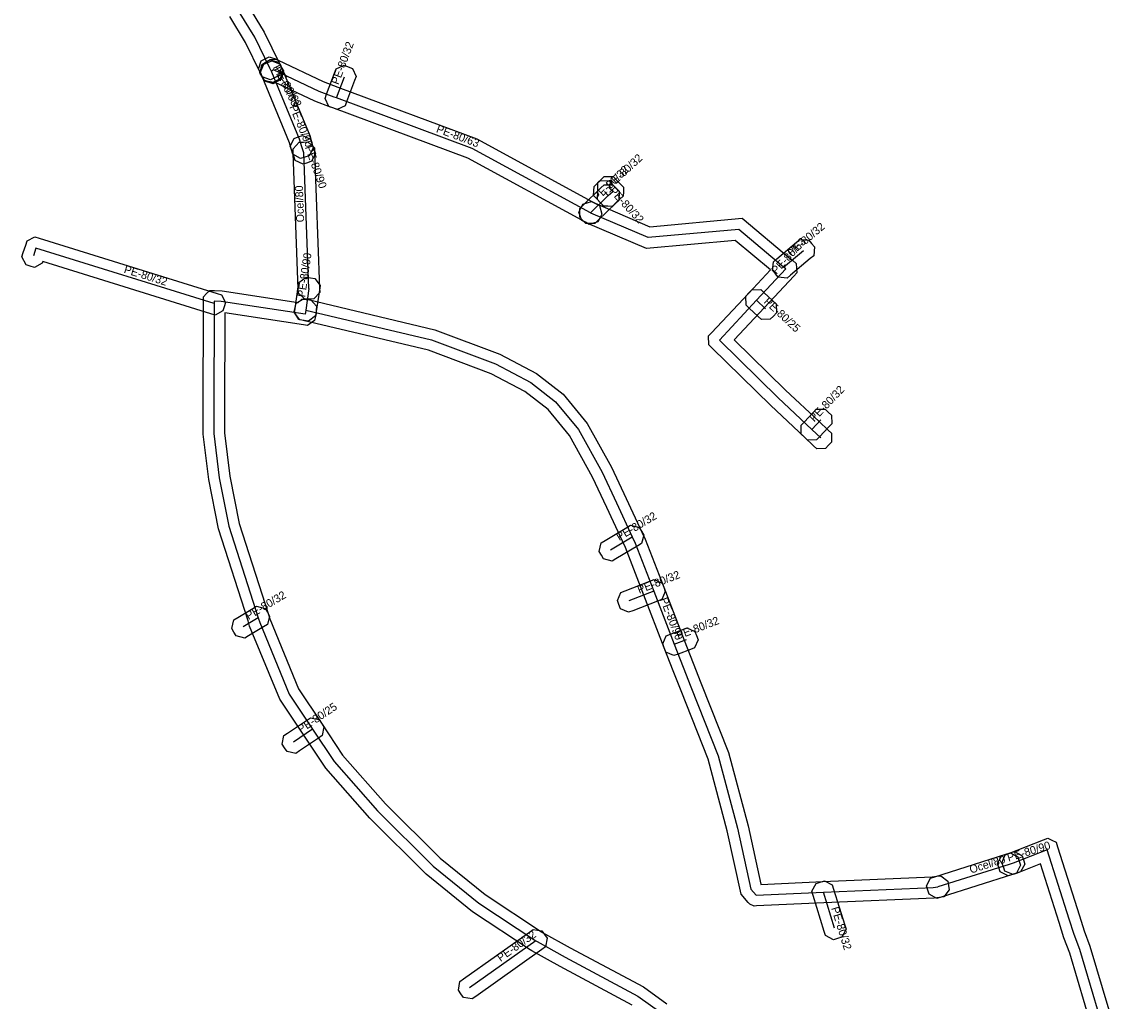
# Model space of a CAD drawing. Extents: x -569373 to -565022, y -1135090 to -1131496.
# Drawn here: x -568946 to -568842.9, y -1132989.8 to -1132898.1 of the extents above; entities that cross this region are included whole.
import ezdxf

# ---------------------------------------------------------------- set-up
doc = ezdxf.new("R2010")
doc.units = 0
for name, color, linetype in [('1', 7, 'Continuous'), ('24', 7, 'Continuous'), ('30', 7, 'Continuous')]:
    doc.layers.add(name, color=color, linetype=linetype)

msp = doc.modelspace()

# ---------------------------------------------------------------- linework, layer by layer
at = {"layer": '1'}
for points in [[(-568924.816, -1132896.447), (-568923.252, -1132899.009), (-568921.811, -1132901.961), (-568921.63, -1132902.333), (-568921.899, -1132903.117), (-568922.271, -1132903.299), (-568922.643, -1132903.48), (-568923.427, -1132903.211), (-568923.609, -1132902.839), (-568925.008, -1132899.971), (-568926.484, -1132897.553)], [(-568888.759, -1132990.191), (-568895.52, -1132986.587), (-568898.167, -1132985.102), (-568898.327, -1132985.004), (-568903.711, -1132981.458), (-568908.079, -1132977.925), (-568913.349, -1132972.685), (-568917.485, -1132967.98), (-568919.542, -1132964.895), (-568921.797, -1132961.512), (-568924.61, -1132954.672), (-568924.763, -1132954.194), (-568927.53, -1132945.551), (-568928.448, -1132940.929), (-568928.97, -1132936.679), (-568928.96, -1132934.517), (-568928.95, -1132924.45), (-568928.95, -1132924.23), (-568928.95, -1132923.807), (-568928.647, -1132923.513), (-568928.343, -1132923.218), (-568927.921, -1132923.23), (-568927.18, -1132923.252), (-568920.055, -1132924.331), (-568919.729, -1132924.032), (-568919.315, -1132924.051), (-568918.901, -1132924.07), (-568918.342, -1132924.681), (-568918.361, -1132925.095), (-568918.375, -1132925.408), (-568918.437, -1132925.669), (-568918.526, -1132926.049), (-568919.174, -1132926.487), (-568919.56, -1132926.429), (-568926.951, -1132925.31), (-568926.96, -1132934.523), (-568926.97, -1132936.561), (-568926.472, -1132940.611), (-568925.59, -1132945.049), (-568922.857, -1132953.586), (-568922.73, -1132953.988), (-568920.023, -1132960.568), (-568917.878, -1132963.785), (-568915.895, -1132966.76), (-568911.891, -1132971.315), (-568906.741, -1132976.435), (-568902.529, -1132979.842), (-568897.253, -1132983.316), (-568897.153, -1132983.378), (-568894.56, -1132984.833), (-568887.701, -1132988.489), (-568885.491, -1132990.075)], [(-568844.847, -1132995.079), (-568847.737, -1132985.313), (-568848.284, -1132983.902), (-568848.746, -1132982.443), (-568850.482, -1132976.967), (-568852.669, -1132977.813), (-568853.055, -1132977.962), (-568853.813, -1132977.627), (-568853.963, -1132977.241), (-568854.112, -1132976.855), (-568853.777, -1132976.097), (-568853.391, -1132975.947), (-568850.211, -1132974.717), (-568849.807, -1132974.561), (-568849.417, -1132974.748), (-568849.027, -1132974.936), (-568848.897, -1132975.348), (-568846.84, -1132981.839), (-568846.396, -1132983.238), (-568845.843, -1132984.667), (-568842.933, -1132994.501)]]:
    msp.add_lwpolyline(points, dxfattribs=at)
for points in [[(-568923.279, -1132903.498), (-568923.464, -1132903.127), (-568923.484, -1132903.087), (-568923.604, -1132902.847), (-568923.79, -1132902.477), (-568923.528, -1132901.691), (-568923.157, -1132901.506), (-568922.787, -1132901.32), (-568922.001, -1132901.582), (-568921.816, -1132901.953), (-568921.696, -1132902.193), (-568921.676, -1132902.233), (-568921.49, -1132902.603), (-568921.752, -1132903.389), (-568922.123, -1132903.574), (-568922.493, -1132903.76)], [(-568923.193, -1132903.618), (-568923.394, -1132903.256), (-568923.444, -1132903.166), (-568923.645, -1132902.804), (-568923.418, -1132902.007), (-568923.056, -1132901.806), (-568922.694, -1132901.605), (-568921.897, -1132901.832), (-568921.696, -1132902.194), (-568921.646, -1132902.284), (-568921.445, -1132902.646), (-568921.672, -1132903.443), (-568922.034, -1132903.644), (-568922.396, -1132903.845)], [(-568918.488, -1132905.493), (-568922.293, -1132903.693), (-568922.372, -1132903.744), (-568923.182, -1132903.572), (-568923.408, -1132903.225), (-568923.634, -1132902.878), (-568923.462, -1132902.068), (-568923.115, -1132901.842), (-568922.915, -1132901.712), (-568922.697, -1132901.57), (-568922.177, -1132901.535), (-568921.942, -1132901.646), (-568917.712, -1132903.647), (-568916.335, -1132904.155), (-568916.103, -1132904.246), (-568903.324, -1132909.008), (-568892.182, -1132915.072), (-568891.818, -1132915.27), (-568891.584, -1132916.064), (-568891.782, -1132916.428), (-568891.98, -1132916.792), (-568892.774, -1132917.026), (-568893.138, -1132916.828), (-568904.156, -1132910.832), (-568916.817, -1132906.114), (-568917.045, -1132906.025)], [(-568920.567, -1132910.444), (-568920.681, -1132910.046), (-568920.876, -1132909.37), (-568923.444, -1132903.152), (-568923.602, -1132902.769), (-568923.285, -1132902.004), (-568922.902, -1132901.846), (-568922.519, -1132901.688), (-568921.754, -1132902.005), (-568921.596, -1132902.388), (-568918.984, -1132908.71), (-568918.759, -1132909.494), (-568918.645, -1132909.892), (-568919.046, -1132910.617), (-568919.444, -1132910.731), (-568919.842, -1132910.845)], [(-568917.542, -1132905.218), (-568917.397, -1132904.83), (-568916.657, -1132902.85), (-568916.512, -1132902.462), (-568915.758, -1132902.118), (-568915.37, -1132902.263), (-568914.982, -1132902.408), (-568914.638, -1132903.162), (-568914.783, -1132903.55), (-568915.523, -1132905.53), (-568915.668, -1132905.918), (-568916.422, -1132906.262), (-568916.81, -1132906.117), (-568917.198, -1132905.972)], [(-568920.335, -1132911.033), (-568920.473, -1132910.642), (-568920.663, -1132910.102), (-568920.801, -1132909.711), (-568920.443, -1132908.965), (-568920.052, -1132908.827), (-568919.661, -1132908.689), (-568918.915, -1132909.047), (-568918.777, -1132909.438), (-568918.587, -1132909.978), (-568918.449, -1132910.369), (-568918.807, -1132911.115), (-568919.198, -1132911.253), (-568919.589, -1132911.391)], [(-568920.044, -1132923.481), (-568920.059, -1132923.067), (-568920.529, -1132910.347), (-568920.544, -1132909.933), (-568919.981, -1132909.326), (-568919.567, -1132909.311), (-568919.153, -1132909.296), (-568918.546, -1132909.859), (-568918.531, -1132910.273), (-568918.061, -1132922.993), (-568918.046, -1132923.407), (-568918.609, -1132924.014), (-568919.023, -1132924.029), (-568919.437, -1132924.044)], [(-568893.655, -1132915.524), (-568893.358, -1132915.234), (-568891.688, -1132913.604), (-568891.392, -1132913.315), (-568890.564, -1132913.325), (-568890.274, -1132913.622), (-568889.985, -1132913.918), (-568889.995, -1132914.746), (-568890.292, -1132915.036), (-568891.962, -1132916.666), (-568892.258, -1132916.955), (-568893.086, -1132916.945), (-568893.376, -1132916.648), (-568893.665, -1132916.352)], [(-568891.444, -1132915.302), (-568891.725, -1132914.998), (-568892.085, -1132914.608), (-568892.366, -1132914.304), (-568892.332, -1132913.476), (-568892.028, -1132913.195), (-568891.724, -1132912.914), (-568890.896, -1132912.948), (-568890.615, -1132913.252), (-568890.255, -1132913.642), (-568889.974, -1132913.946), (-568890.008, -1132914.774), (-568890.312, -1132915.055), (-568890.616, -1132915.336)], [(-568892.005, -1132914.696), (-568891.974, -1132913.873), (-568891.974, -1132913.868), (-568891.965, -1132913.113), (-568891.668, -1132912.824), (-568891.371, -1132912.535), (-568890.543, -1132912.545), (-568890.254, -1132912.842), (-568889.864, -1132913.242), (-568889.57, -1132913.544), (-568889.58, -1132913.965), (-568889.591, -1132914.387), (-568889.9, -1132914.673), (-568890.31, -1132915.053), (-568890.614, -1132915.335), (-568891.442, -1132915.304), (-568891.723, -1132915)], [(-568892.583, -1132914.87), (-568892.225, -1132915.05), (-568887.089, -1132917.251), (-568878.447, -1132916.456), (-568873.922, -1132920.25), (-568873.707, -1132920.426), (-568873.371, -1132920.701), (-568873.342, -1132921.134), (-568873.313, -1132921.566), (-568873.61, -1132921.883), (-568876.36, -1132924.823), (-568879.183, -1132927.84), (-568874.387, -1132932.549), (-568871.235, -1132935.512), (-568870.385, -1132936.312), (-568870.083, -1132936.596), (-568870.058, -1132937.423), (-568870.342, -1132937.725), (-568870.626, -1132938.027), (-568871.453, -1132938.052), (-568871.755, -1132937.768), (-568872.605, -1132936.968), (-568875.773, -1132933.991), (-568881.281, -1132928.584), (-568881.571, -1132928.299), (-568881.588, -1132927.484), (-568881.31, -1132927.187), (-568877.82, -1132923.457), (-568875.794, -1132921.291), (-568879.093, -1132918.524), (-568887.411, -1132919.289), (-568893.061, -1132916.868), (-568893.107, -1132916.844), (-568893.478, -1132916.659), (-568893.74, -1132915.873), (-568893.554, -1132915.503), (-568893.369, -1132915.132)], [(-568928.246, -1132925.405), (-568943.997, -1132920.519), (-568944.046, -1132920.675), (-568944.781, -1132921.056), (-568945.176, -1132920.931), (-568945.571, -1132920.806), (-568945.952, -1132920.071), (-568945.827, -1132919.676), (-568945.603, -1132918.968), (-568945.479, -1132918.575), (-568944.748, -1132918.193), (-568944.354, -1132918.315), (-568927.654, -1132923.495), (-568927.258, -1132923.618), (-568926.872, -1132924.35), (-568926.995, -1132924.746), (-568927.118, -1132925.142), (-568927.85, -1132925.528)], [(-568875.52, -1132920.52), (-568875.203, -1132920.254), (-568873.343, -1132918.694), (-568873.025, -1132918.428), (-568872.2, -1132918.5), (-568871.934, -1132918.817), (-568871.668, -1132919.135), (-568871.74, -1132919.96), (-568872.057, -1132920.226), (-568873.917, -1132921.786), (-568874.235, -1132922.052), (-568875.06, -1132921.98), (-568875.326, -1132921.663), (-568875.592, -1132921.345)], [(-568918.01, -1132922.767), (-568918.071, -1132923.177), (-568918.371, -1132925.197), (-568918.432, -1132925.607), (-568919.097, -1132926.1), (-568919.507, -1132926.039), (-568919.917, -1132925.978), (-568920.41, -1132925.313), (-568920.349, -1132924.903), (-568920.049, -1132922.883), (-568919.988, -1132922.473), (-568919.323, -1132921.98), (-568918.913, -1132922.041), (-568918.503, -1132922.102)], [(-568876.707, -1132923.128), (-568876.405, -1132923.412), (-568875.565, -1132924.202), (-568875.263, -1132924.486), (-568875.238, -1132925.313), (-568875.522, -1132925.615), (-568875.806, -1132925.917), (-568876.633, -1132925.942), (-568876.935, -1132925.658), (-568877.775, -1132924.868), (-568878.077, -1132924.584), (-568878.102, -1132923.757), (-568877.818, -1132923.455), (-568877.534, -1132923.153)], [(-568919.531, -1132923.981), (-568919.128, -1132924.077), (-568907.267, -1132926.902), (-568901.159, -1132929.196), (-568897.728, -1132931.005), (-568895.229, -1132932.927), (-568892.97, -1132935.685), (-568890.679, -1132939.794), (-568889.314, -1132942.707), (-568887.84, -1132945.872), (-568887.539, -1132946.519), (-568885.797, -1132951.04), (-568883.877, -1132955.999), (-568883.049, -1132958.146), (-568882.313, -1132960.003), (-568879.729, -1132966.526), (-568877.898, -1132973.385), (-568876.709, -1132978.871), (-568876.7, -1132978.88), (-568870.874, -1132978.621), (-568860.637, -1132978.173), (-568860.219, -1132978.118), (-568859.809, -1132978.065), (-568859.152, -1132978.57), (-568859.098, -1132978.981), (-568859.045, -1132979.391), (-568859.55, -1132980.048), (-568859.961, -1132980.102), (-568860.463, -1132980.167), (-568870.786, -1132980.619), (-568877.086, -1132980.899), (-568877.311, -1132980.909), (-568877.726, -1132980.734), (-568877.876, -1132980.566), (-568878.551, -1132979.809), (-568879.842, -1132973.855), (-568881.631, -1132967.154), (-568884.173, -1132960.739), (-568884.911, -1132958.874), (-568885.743, -1132956.721), (-568887.663, -1132951.76), (-568889.381, -1132947.301), (-568889.654, -1132946.716), (-568891.126, -1132943.553), (-568892.461, -1132940.706), (-568894.63, -1132936.815), (-568896.631, -1132934.373), (-568898.812, -1132932.695), (-568901.981, -1132931.024), (-568907.853, -1132928.818), (-568919.592, -1132926.023), (-568919.995, -1132925.927), (-568920.429, -1132925.221), (-568920.333, -1132924.818), (-568920.237, -1132924.415)], [(-568872.929, -1132935.848), (-568872.643, -1132935.549), (-568871.783, -1132934.649), (-568871.497, -1132934.35), (-568870.668, -1132934.331), (-568870.369, -1132934.617), (-568870.07, -1132934.903), (-568870.051, -1132935.732), (-568870.337, -1132936.031), (-568871.197, -1132936.931), (-568871.483, -1132937.23), (-568872.312, -1132937.249), (-568872.611, -1132936.963), (-568872.91, -1132936.677)], [(-568891.654, -1132946.864), (-568891.299, -1132946.652), (-568889.26, -1132945.435), (-568888.904, -1132945.223), (-568888.1, -1132945.426), (-568887.888, -1132945.781), (-568887.676, -1132946.137), (-568887.879, -1132946.941), (-568888.234, -1132947.153), (-568890.273, -1132948.37), (-568890.629, -1132948.582), (-568891.433, -1132948.379), (-568891.645, -1132948.024), (-568891.857, -1132947.668)], [(-568885.984, -1132952.184), (-568886.37, -1132952.333), (-568888.7, -1132953.233), (-568889.086, -1132953.382), (-568889.844, -1132953.046), (-568889.993, -1132952.66), (-568890.142, -1132952.274), (-568889.806, -1132951.516), (-568889.42, -1132951.367), (-568887.09, -1132950.467), (-568886.704, -1132950.318), (-568885.946, -1132950.654), (-568885.797, -1132951.04), (-568885.648, -1132951.426)], [(-568922.942, -1132954.537), (-568923.298, -1132954.749), (-568924.708, -1132955.589), (-568925.064, -1132955.801), (-568925.867, -1132955.598), (-568926.079, -1132955.242), (-568926.291, -1132954.886), (-568926.088, -1132954.083), (-568925.732, -1132953.871), (-568924.322, -1132953.031), (-568923.966, -1132952.819), (-568923.163, -1132953.022), (-568922.951, -1132953.378), (-568922.739, -1132953.734)], [(-568885.554, -1132955.574), (-568885.167, -1132955.426), (-568884.017, -1132954.986), (-568883.63, -1132954.838), (-568882.874, -1132955.176), (-568882.726, -1132955.563), (-568882.578, -1132955.95), (-568882.916, -1132956.706), (-568883.303, -1132956.854), (-568884.453, -1132957.294), (-568884.84, -1132957.442), (-568885.596, -1132957.104), (-568885.744, -1132956.717), (-568885.892, -1132956.33)], [(-568917.809, -1132964.94), (-568918.153, -1132965.171), (-568919.943, -1132966.371), (-568920.287, -1132966.601), (-568921.1, -1132966.441), (-568921.331, -1132966.097), (-568921.561, -1132965.753), (-568921.401, -1132964.94), (-568921.057, -1132964.709), (-568919.267, -1132963.509), (-568918.923, -1132963.279), (-568918.11, -1132963.439), (-568917.879, -1132963.783), (-568917.649, -1132964.127)], [(-568852.723, -1132977.828), (-568853.118, -1132977.953), (-568859.788, -1132980.063), (-568860.183, -1132980.188), (-568860.918, -1132979.807), (-568861.043, -1132979.412), (-568861.168, -1132979.017), (-568860.787, -1132978.282), (-568860.392, -1132978.157), (-568853.722, -1132976.047), (-568853.327, -1132975.922), (-568852.592, -1132976.303), (-568852.467, -1132976.698), (-568852.342, -1132977.093)], [(-568852.34, -1132977.714), (-568852.736, -1132977.836), (-568853.126, -1132977.956), (-568853.522, -1132978.078), (-568854.254, -1132977.69), (-568854.376, -1132977.294), (-568854.498, -1132976.898), (-568854.11, -1132976.166), (-568853.714, -1132976.044), (-568853.324, -1132975.924), (-568852.928, -1132975.802), (-568852.196, -1132976.19), (-568852.074, -1132976.586), (-568851.952, -1132976.982)], [(-568870.624, -1132983.681), (-568870.746, -1132983.285), (-568871.786, -1132979.915), (-568871.908, -1132979.519), (-568871.521, -1132978.786), (-568871.125, -1132978.664), (-568870.729, -1132978.542), (-568869.996, -1132978.929), (-568869.874, -1132979.325), (-568868.834, -1132982.695), (-568868.712, -1132983.091), (-568869.099, -1132983.824), (-568869.495, -1132983.946), (-568869.891, -1132984.068)], [(-568896.873, -1132984.736), (-568897.211, -1132984.976), (-568903.411, -1132989.376), (-568903.749, -1132989.615), (-568904.566, -1132989.477), (-568904.806, -1132989.139), (-568905.045, -1132988.801), (-568904.907, -1132987.984), (-568904.569, -1132987.744), (-568898.369, -1132983.344), (-568898.031, -1132983.105), (-568897.214, -1132983.243), (-568896.974, -1132983.581), (-568896.735, -1132983.919)]]:
    msp.add_lwpolyline(points, close=True, dxfattribs=at)
at = {"layer": '24'}
for points in [[(-568922.71, -1132902.4), (-568924.13, -1132899.49), (-568925.65, -1132897)], [(-568922.57, -1132902.68), (-568922.59, -1132902.64), (-568922.71, -1132902.4)], [(-568892.66, -1132915.95), (-568903.74, -1132909.92), (-568916.46, -1132905.18), (-568916.69, -1132905.09), (-568918.1, -1132904.57), (-568922.37, -1132902.55), (-568922.57, -1132902.68)], [(-568922.52, -1132902.77), (-568922.57, -1132902.68)], [(-568919.72, -1132909.77), (-568919.93, -1132909.04), (-568922.52, -1132902.77)], [(-568916.46, -1132905.18), (-568915.72, -1132903.2)], [(-568919.53, -1132910.31), (-568919.72, -1132909.77)], [(-568919.06, -1132923.03), (-568919.53, -1132910.31)], [(-568892.66, -1132915.95), (-568890.99, -1132914.32)], [(-568890.99, -1132914.32), (-568891.35, -1132913.93)], [(-568890.99, -1132914.32), (-568890.58, -1132913.94), (-568890.97, -1132913.54)], [(-568871.07, -1132937.04), (-568871.92, -1132936.24), (-568875.08, -1132933.27), (-568880.58, -1132927.87), (-568877.09, -1132924.14), (-568874.34, -1132921.2), (-568874.56, -1132921.02), (-568878.77, -1132917.49), (-568887.25, -1132918.27), (-568892.64, -1132915.96), (-568892.66, -1132915.95)], [(-568927.95, -1132924.45), (-568944.65, -1132919.27), (-568944.874, -1132919.978)], [(-568874.56, -1132921.02), (-568872.7, -1132919.46)], [(-568919.06, -1132923.03), (-568919.36, -1132925.05)], [(-568919.36, -1132925.05), (-568919.37, -1132925.27), (-568919.41, -1132925.44), (-568927.27, -1132924.25), (-568927.95, -1132924.23), (-568927.95, -1132924.45), (-568927.96, -1132934.52), (-568927.97, -1132936.62), (-568927.46, -1132940.77), (-568926.56, -1132945.3), (-568923.81, -1132953.89), (-568923.67, -1132954.33), (-568920.91, -1132961.04), (-568918.71, -1132964.34), (-568916.69, -1132967.37), (-568912.62, -1132972), (-568907.41, -1132977.18), (-568903.12, -1132980.65), (-568897.79, -1132984.16), (-568897.66, -1132984.24), (-568895.04, -1132985.71), (-568888.23, -1132989.34), (-568886.07, -1132990.89)], [(-568877.09, -1132924.14), (-568876.25, -1132924.93)], [(-568919.36, -1132925.05), (-568907.56, -1132927.86), (-568901.57, -1132930.11), (-568898.27, -1132931.85), (-568895.93, -1132933.65), (-568893.8, -1132936.25), (-568891.57, -1132940.25), (-568890.22, -1132943.13), (-568888.747, -1132946.294), (-568888.46, -1132946.91), (-568886.73, -1132951.4), (-568884.81, -1132956.36), (-568883.98, -1132958.51), (-568883.243, -1132960.371), (-568880.68, -1132966.84), (-568878.87, -1132973.62), (-568877.63, -1132979.34), (-568877.13, -1132979.9), (-568870.83, -1132979.62), (-568860.55, -1132979.17), (-568860.09, -1132979.11)], [(-568871.92, -1132936.24), (-568871.06, -1132935.34)], [(-568890.786, -1132947.511), (-568888.747, -1132946.294)], [(-568886.73, -1132951.4), (-568889.06, -1132952.3)], [(-568923.81, -1132953.89), (-568925.22, -1132954.73)], [(-568884.81, -1132956.36), (-568883.66, -1132955.92)], [(-568918.71, -1132964.34), (-568920.5, -1132965.54)], [(-568843.89, -1132994.79), (-568846.79, -1132984.99), (-568847.34, -1132983.57), (-568847.793, -1132982.141), (-568849.85, -1132975.65), (-568853.03, -1132976.88)], [(-568853.42, -1132977), (-568860.09, -1132979.11)], [(-568853.03, -1132976.88), (-568853.42, -1132977)], [(-568869.79, -1132982.99), (-568870.83, -1132979.62)], [(-568897.79, -1132984.16), (-568903.99, -1132988.56)]]:
    msp.add_lwpolyline(points, dxfattribs=at)

# ---------------------------------------------------------------- texts
at = {"layer": '30'}
for s, rotation, p in [('PE-80/32', 69.50741, (-568916.29, -1132903.99)), ('PE-80/63', 296.56505, (-568922.462, -1132902.295)), ('PE-80/63', 299.0546, (-568922.369, -1132902.481)), ('PE-80/90', 292.44445, (-568920.899, -1132906.01)), ('PE-80/63', 339.56252, (-568907.181, -1132908.363)), ('PE-80/90', 289.38452, (-568919.442, -1132909.793)), ('PE-80/32', 42.82526, (-568890.78, -1132913.74)), ('PE-80/32', 44.30554, (-568891.989, -1132914.9)), ('Ocel/80', 92.1161, (-568919.497, -1132916.82)), ('PE-80/32', 312.70939, (-568890.97, -1132913.925)), ('PE-80/32', 39.98689, (-568873.83, -1132920.04)), ('PE-80/63', 46.91251, (-568875.245, -1132921.754)), ('PE-80/90', 81.55247, (-568919.417, -1132923.889)), ('PE-80/32', 342.76717, (-568936.455, -1132921.55)), ('PE-80/25', 316.75699, (-568876.47, -1132924.335)), ('PE-80/32', 46.30195, (-568871.69, -1132935.59)), ('PE-80/32', 30.83134, (-568889.966, -1132946.703)), ('PE-80/32', 21.11986, (-568888.095, -1132951.65)), ('PE-80/32', 30.78415, (-568924.715, -1132954.11)), ('PE-80/90', 291.16126, (-568886.16, -1132952.156)), ('PE-80/32', 20.93729, (-568884.435, -1132955.94)), ('PE-80/25', 33.83755, (-568919.805, -1132964.74)), ('PE-80/90', 17.10273, (-568853.473, -1132976.755)), ('Ocel/80', 17.55434, (-568857.003, -1132977.87)), ('PE-80/32', 287.15051, (-568870.11, -1132981.105)), ('PE-80/32', 35.36246, (-568901.09, -1132986.16))]:
    msp.add_text(s, height=0.75, rotation=rotation, dxfattribs=at).set_placement(p)

doc.saveas('drawing.dxf')
